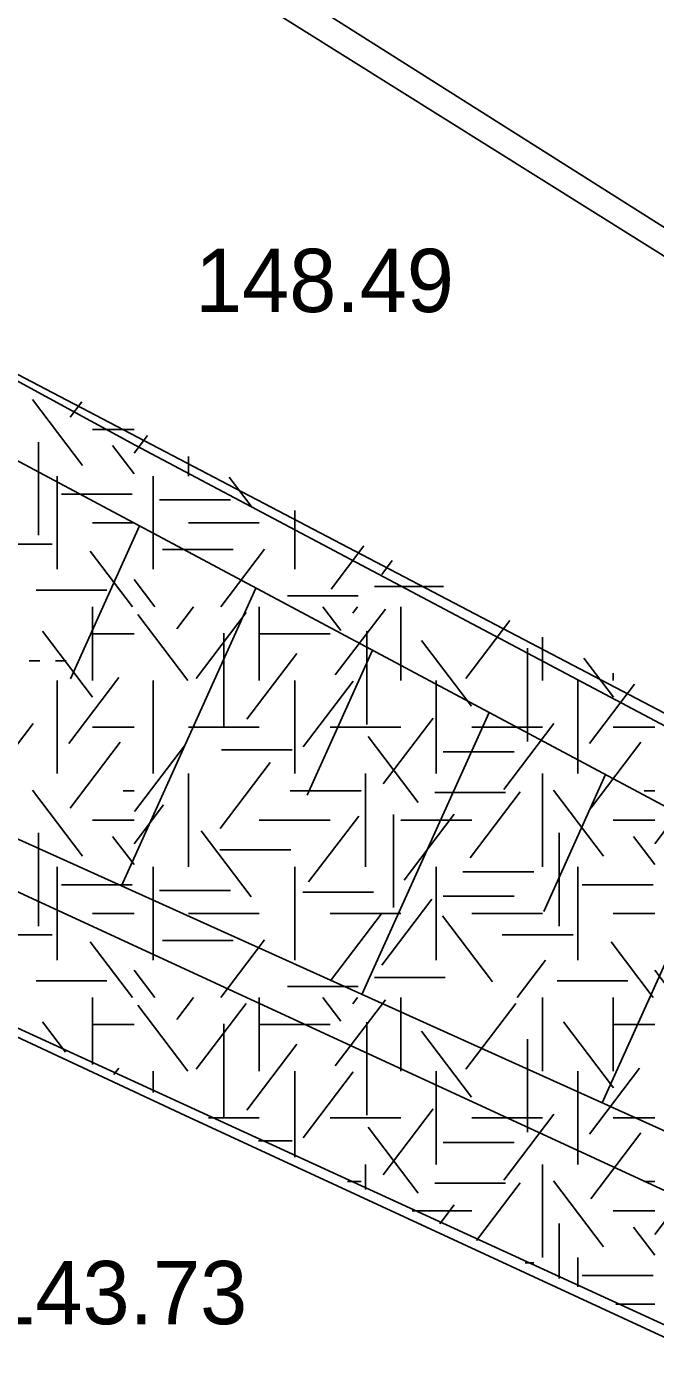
# Model space of a CAD drawing. Extents: x 419677 to 421689, y 4450851 to 4452923.
# Drawn here: x 420344.82 to 420356.74, y 4451978.52 to 4452004.01 of the extents above; entities that cross this region are included whole.
import ezdxf

# ---------------------------------------------------------------- set-up
doc = ezdxf.new("R2010")
doc.units = 0
for name, color, linetype in [('AA_HH', 7, 'Continuous'), ('Level 41', 7, 'Continuous'), ('Level 62', 7, 'Continuous'), ('Level 9', 7, 'Continuous')]:
    doc.layers.add(name, color=color, linetype=linetype)

msp = doc.modelspace()

# ---------------------------------------------------------------- linework, layer by layer
at = {"layer": 'AA_HH'}
for p, q in [((420346.954, 4451994.546), (420345.646, 4451991.646)), ((420349.165, 4451993.367), (420346.616, 4451987.719)), ((420351.375, 4451992.188), (420350.135, 4451989.439)), ((420344.863, 4451991.987), (420345.063, 4451991.987)), ((420345.363, 4451991.987), (420345.563, 4451991.987)), ((420353.586, 4451991.009), (420351.173, 4451985.662)), ((420355.797, 4451989.83), (420354.625, 4451987.232)), ((420358.008, 4451988.651), (420355.731, 4451983.606))]:
    msp.add_line(p, q, dxfattribs=at)
for points in [[(420420.283, 4451972.04), (420421.029, 4451970.095), (420421.342, 4451968.715), (420420.96, 4451967.485), (420420.456, 4451967.019), (420419.682, 4451966.656), (420419.467, 4451966.604), (420419.102, 4451966.589), (420380.556, 4451986.723), (420357.561, 4451999.25), (420318.688, 4452023.585), (420304.823, 4452033.943), (420285.337, 4452050.002), (420272.264, 4452064.398), (420263.435, 4452076.857), (420254.665, 4452090.863), (420245.178, 4452107.602), (420239.444, 4452119.113), (420237.151, 4452126.743), (420229.958, 4452160.587), (420223.737, 4452191.2), (420219.459, 4452205.797)], [(420397.569, 4451969.565), (420368.162, 4451984.791), (420346.871, 4451996.077), (420325.677, 4452007.623), (420307.1, 4452017.8), (420297.551, 4452023.383), (420287.987, 4452030.11), (420276.408, 4452038.563), (420264.859, 4452049.332), (420260.081, 4452053.957), (420259.882, 4452054.112), (420260.728, 4452041.699), (420259.985, 4452032.196), (420258.843, 4452024.529), (420255.051, 4452011.924), (420250.679, 4452002.57), (420243.311, 4451990.758), (420238.509, 4451984.736), (420246.006, 4451983.783), (420257.774, 4451981.835), (420271.403, 4451978.695), (420279.405, 4451976.372)], [(420438.02, 4451947.439), (420433.413, 4451950.307), (420401.754, 4451966.128), (420364.854, 4451984.999), (420328.536, 4452004.369), (420296.842, 4452019.746), (420270.508, 4452033.174), (420265.237, 4452035.449), (420263.701, 4452035.377)], [(420262.475, 4452026.146), (420281.038, 4452017.637), (420307.521, 4452005.58), (420333.161, 4451993.79), (420361.041, 4451981.209), (420384.615, 4451970.223), (420409.297, 4451959.288), (420435.147, 4451947.432), (420438.02, 4451947.439)], [(420497.355, 4451918.073), (420480.964, 4451925.058), (420460.145, 4451935.145), (420426.277, 4451950.923), (420396.304, 4451964.212), (420364.7, 4451978.35), (420337.466, 4451990.917), (420308.204, 4452004.292), (420278.592, 4452017.702), (420262.185, 4452024.997)], [(420261.585, 4452022.627), (420280.922, 4452013.915), (420311.822, 4452000.182), (420347.823, 4451983.366), (420379.279, 4451968.819), (420400.872, 4451959.31), (420439.168, 4451941.96), (420472.621, 4451926.744), (420501.172, 4451913.665)]]:
    msp.add_lwpolyline(points, dxfattribs=at)
at = {"layer": 'Level 41'}
for p, q in [((420345.878, 4451995.693), (420344.929, 4451996.942)), ((420345.639, 4451996.605), (420345.86, 4451996.896)), ((420346.064, 4451996.373), (420346.852, 4451996.373)), ((420346.852, 4451995.927), (420347.105, 4451996.26)), ((420345.039, 4451996.135), (420345.039, 4451994.367)), ((420346.852, 4451995.533), (420346.446, 4451996.067)), ((420347.885, 4451995.862), (420347.885, 4451995.49)), ((420345.393, 4451993.722), (420345.393, 4451995.49)), ((420347.214, 4451993.722), (420347.214, 4451995.49)), ((420349.072, 4451994.922), (420348.657, 4451995.468)), ((420345.475, 4451995.147), (420346.818, 4451995.147)), ((420347.337, 4451995.041), (420348.68, 4451995.041)), ((420349.9, 4451993.722), (420349.9, 4451994.834)), ((420346.064, 4451994.606), (420346.852, 4451994.606)), ((420347.885, 4451994.606), (420349.228, 4451994.606)), ((420343.957, 4451994.199), (420345.3, 4451994.199)), ((420346.823, 4451993.013), (420346.021, 4451994.069)), ((420347.391, 4451994.095), (420348.733, 4451994.095)), ((420348.499, 4451993.013), (420349.328, 4451994.104)), ((420350.59, 4451993.346), (420351.212, 4451994.165)), ((420351.55, 4451993.625), (420351.751, 4451993.89)), ((420347.246, 4451993.013), (420346.852, 4451993.531)), ((420344.996, 4451993.325), (420346.339, 4451993.325)), ((420349.761, 4451993.219), (420351.104, 4451993.219)), ((420351.413, 4451993.394), (420352.723, 4451993.394)), ((420346.064, 4451993.013), (420346.064, 4451991.615)), ((420346.064, 4451993.013), (420346.064, 4451991.615)), ((420347.662, 4451992.596), (420347.979, 4451993.013)), ((420349.228, 4451993.013), (420349.228, 4451991.615)), ((420350.777, 4451992.561), (420350.433, 4451993.013)), ((420350.67, 4451991.719), (420351.62, 4451992.969)), ((420351.003, 4451992.893), (420351.094, 4451993.013)), ((420351.914, 4451993.013), (420351.914, 4451991.615)), ((420347.873, 4451991.615), (420346.924, 4451992.865)), ((420348.033, 4451991.65), (420348.982, 4451992.9)), ((420353.147, 4451991.65), (420353.983, 4451992.751)), ((420346.065, 4451991.299), (420345.116, 4451992.548)), ((420346.064, 4451992.499), (420346.852, 4451992.499)), ((420348.553, 4451992.511), (420348.553, 4451990.744)), ((420349.228, 4451992.499), (420350.571, 4451992.499)), ((420351.27, 4451992.546), (420351.27, 4451990.779)), ((420354.6, 4451992.436), (420354.6, 4451991.615)), ((420353.254, 4451991.124), (420352.305, 4451992.373)), ((420354.318, 4451992.225), (420354.318, 4451990.458)), ((420348.993, 4451990.878), (420349.942, 4451992.128)), ((420355.944, 4451991.299), (420355.384, 4451992.036)), ((420345.613, 4451990.422), (420346.562, 4451991.672)), ((420355.943, 4451991.751), (420355.943, 4451991.615)), ((420355.943, 4451991.751), (420355.943, 4451991.615)), ((420345.393, 4451991.615), (420345.393, 4451989.848)), ((420345.393, 4451991.615), (420345.393, 4451989.848)), ((420347.214, 4451989.848), (420347.214, 4451991.615)), ((420349.9, 4451991.615), (420349.9, 4451989.848)), ((420350.059, 4451990.353), (420351.008, 4451991.603)), ((420352.586, 4451991.615), (420352.586, 4451989.848)), ((420355.272, 4451991.615), (420355.272, 4451989.848)), ((420355.272, 4451991.615), (420355.272, 4451989.848)), ((420355.492, 4451990.422), (420356.345, 4451991.546)), ((420351.576, 4451989.652), (420352.527, 4451990.901)), ((420343.988, 4451989.547), (420344.937, 4451990.797)), ((420346.064, 4451990.731), (420346.852, 4451990.731)), ((420347.885, 4451990.731), (420349.228, 4451990.731)), ((420350.571, 4451990.731), (420351.914, 4451990.731)), ((420353.257, 4451990.731), (420354.6, 4451990.731)), ((420353.867, 4451989.547), (420354.816, 4451990.797)), ((420355.943, 4451990.731), (420356.731, 4451990.731)), ((420345.639, 4451989.196), (420346.589, 4451990.445)), ((420352.242, 4451989.302), (420351.292, 4451990.551)), ((420355.518, 4451989.196), (420356.468, 4451990.445)), ((420346.862, 4451989.127), (420347.811, 4451990.376)), ((420348.509, 4451990.297), (420349.852, 4451990.297)), ((420352.717, 4451990.261), (420354.06, 4451990.261)), ((420348.487, 4451988.81), (420349.436, 4451990.06)), ((420347.885, 4451989.848), (420347.885, 4451988.081)), ((420351.243, 4451989.848), (420351.243, 4451988.081)), ((420354.6, 4451989.848), (420354.6, 4451988.081)), ((420345.878, 4451988.284), (420344.929, 4451989.533)), ((420346.648, 4451989.524), (420346.852, 4451989.524)), ((420349.815, 4451989.524), (420351.158, 4451989.524)), ((420352.557, 4451989.491), (420353.9, 4451989.491)), ((420353.227, 4451988.25), (420354.177, 4451989.5)), ((420355.757, 4451988.284), (420354.808, 4451989.533)), ((420356.527, 4451989.524), (420356.731, 4451989.524)), ((420346.852, 4451988.518), (420347.411, 4451989.254)), ((420356.731, 4451988.518), (420357.29, 4451989.254)), ((420346.064, 4451988.964), (420346.852, 4451988.964)), ((420349.228, 4451988.964), (420350.571, 4451988.964)), ((420350.164, 4451987.794), (420351.114, 4451989.044)), ((420351.775, 4451989.076), (420351.775, 4451987.308)), ((420351.914, 4451988.964), (420353.257, 4451988.964)), ((420351.975, 4451987.83), (420352.924, 4451989.079)), ((420355.943, 4451988.964), (420356.731, 4451988.964)), ((420345.039, 4451988.726), (420345.039, 4451986.958)), ((420346.852, 4451988.124), (420346.446, 4451988.658)), ((420349.072, 4451987.513), (420348.123, 4451988.763)), ((420354.918, 4451988.726), (420354.918, 4451986.958)), ((420356.731, 4451988.124), (420356.325, 4451988.658)), ((420348.482, 4451988.404), (420349.825, 4451988.404)), ((420345.393, 4451986.313), (420345.393, 4451988.081)), ((420347.214, 4451986.313), (420347.214, 4451988.081)), ((420349.9, 4451986.313), (420349.9, 4451988.081)), ((420352.586, 4451986.313), (420352.586, 4451988.081)), ((420353.091, 4451987.983), (420354.434, 4451987.983)), ((420355.272, 4451986.313), (420355.272, 4451988.081)), ((420345.475, 4451987.738), (420346.818, 4451987.738)), ((420347.337, 4451987.632), (420348.68, 4451987.632)), ((420350.054, 4451987.598), (420351.397, 4451987.598)), ((420355.354, 4451987.738), (420356.697, 4451987.738)), ((420351.55, 4451986.216), (420352.499, 4451987.466)), ((420352.717, 4451987.527), (420354.06, 4451987.527)), ((420346.064, 4451987.197), (420346.852, 4451987.197)), ((420347.885, 4451987.197), (420349.228, 4451987.197)), ((420350.571, 4451987.197), (420351.914, 4451987.197)), ((420350.59, 4451985.937), (420351.539, 4451987.186)), ((420353.653, 4451985.902), (420352.703, 4451987.151)), ((420353.257, 4451987.197), (420354.6, 4451987.197)), ((420355.943, 4451987.197), (420356.731, 4451987.197)), ((420343.957, 4451986.79), (420345.3, 4451986.79)), ((420346.823, 4451985.604), (420346.021, 4451986.66)), ((420347.391, 4451986.686), (420348.733, 4451986.686)), ((420348.499, 4451985.604), (420349.328, 4451986.695)), ((420353.836, 4451986.79), (420355.179, 4451986.79)), ((420356.702, 4451985.604), (420355.9, 4451986.66)), ((420354.119, 4451985.604), (420354.656, 4451986.31)), ((420347.246, 4451985.604), (420346.852, 4451986.122)), ((420357.125, 4451985.604), (420356.731, 4451986.122)), ((420344.996, 4451985.916), (420346.339, 4451985.916)), ((420349.761, 4451985.81), (420351.104, 4451985.81)), ((420351.413, 4451985.985), (420352.756, 4451985.985)), ((420354.875, 4451985.916), (420356.218, 4451985.916)), ((420346.064, 4451985.604), (420346.064, 4451984.33)), ((420346.064, 4451985.604), (420346.064, 4451984.33)), ((420347.662, 4451985.187), (420347.979, 4451985.604)), ((420349.228, 4451985.604), (420349.228, 4451984.206)), ((420350.777, 4451985.152), (420350.433, 4451985.604)), ((420350.67, 4451984.31), (420351.62, 4451985.56)), ((420351.003, 4451985.484), (420351.094, 4451985.604)), ((420351.914, 4451985.604), (420351.914, 4451984.206)), ((420354.6, 4451985.604), (420354.6, 4451984.206)), ((420355.943, 4451985.604), (420355.943, 4451984.206)), ((420355.943, 4451985.604), (420355.943, 4451984.206)), ((420347.873, 4451984.206), (420346.924, 4451985.456)), ((420348.033, 4451984.241), (420348.982, 4451985.491)), ((420353.147, 4451984.241), (420354.096, 4451985.491)), ((420345.553, 4451984.564), (420345.116, 4451985.139)), ((420346.064, 4451985.09), (420346.852, 4451985.09)), ((420348.553, 4451985.102), (420348.553, 4451983.335)), ((420349.228, 4451985.09), (420350.571, 4451985.09)), ((420351.27, 4451985.137), (420351.27, 4451983.37)), ((420355.944, 4451983.89), (420354.995, 4451985.139)), ((420355.943, 4451985.09), (420356.731, 4451985.09)), ((420353.254, 4451983.715), (420352.305, 4451984.964)), ((420354.318, 4451984.816), (420354.318, 4451983.049)), ((420348.993, 4451983.469), (420349.942, 4451984.719)), ((420346.471, 4451984.144), (420346.562, 4451984.263)), ((420355.492, 4451983.013), (420356.441, 4451984.263)), ((420347.214, 4451983.804), (420347.214, 4451984.206)), ((420349.9, 4451984.206), (420349.9, 4451982.574)), ((420350.059, 4451982.944), (420351.008, 4451984.194)), ((420352.586, 4451984.206), (420352.586, 4451982.439)), ((420355.272, 4451984.206), (420355.272, 4451982.439)), ((420355.272, 4451984.206), (420355.272, 4451982.439)), ((420348.267, 4451983.322), (420349.228, 4451983.322)), ((420350.571, 4451983.322), (420351.914, 4451983.322)), ((420351.576, 4451982.243), (420352.527, 4451983.492)), ((420353.257, 4451983.322), (420354.6, 4451983.322)), ((420353.867, 4451982.138), (420354.816, 4451983.388)), ((420355.943, 4451983.322), (420356.731, 4451983.322)), ((420352.242, 4451981.893), (420351.292, 4451983.142)), ((420355.518, 4451981.787), (420356.468, 4451983.036)), ((420349.215, 4451982.888), (420349.852, 4451982.888)), ((420352.717, 4451982.852), (420354.06, 4451982.852)), ((420351.243, 4451982.439), (420351.243, 4451981.96)), ((420354.6, 4451982.439), (420354.6, 4451980.672)), ((420350.904, 4451982.115), (420351.158, 4451982.115)), ((420352.557, 4451982.082), (420353.9, 4451982.082)), ((420353.346, 4451980.997), (420354.177, 4451982.091)), ((420355.757, 4451980.875), (420354.808, 4451982.124)), ((420356.527, 4451982.115), (420356.731, 4451982.115)), ((420356.731, 4451981.109), (420357.29, 4451981.845)), ((420352.127, 4451981.555), (420353.257, 4451981.555)), ((420352.654, 4451981.314), (420352.924, 4451981.67)), ((420355.943, 4451981.555), (420356.731, 4451981.555)), ((420354.918, 4451981.317), (420354.918, 4451980.278)), ((420356.731, 4451980.715), (420356.325, 4451981.249)), ((420354.27, 4451980.574), (420354.434, 4451980.574)), ((420355.272, 4451980.116), (420355.272, 4451980.672)), ((420355.354, 4451980.329), (420356.697, 4451980.329)), ((420355.988, 4451979.788), (420356.731, 4451979.788))]:
    msp.add_line(p, q, dxfattribs=at)
at = {"layer": 'Level 62'}
for p, q in [((420312.087, 4452014.455), (420412.275, 4451962.014)), ((420367.332, 4451974.612), (420327.12, 4451993.061))]:
    msp.add_line(p, q, dxfattribs=at)
at = {"layer": 'Level 9'}
for q in [(420295.814, 4452038.838), (420298.525, 4452037.123), (420298.525, 4452037.123)]:
    msp.add_line((420374.111, 4451989.328), q, dxfattribs=at)

# ---------------------------------------------------------------- texts
at = {"layer": 'AA_HH'}
msp.add_text('148.49 ', height=1.2, rotation=0.0026, dxfattribs=at).set_placement((420348.011, 4451998.599))
msp.add_text('143.73 ', height=1.2, dxfattribs=at).set_placement((420344.091, 4451979.408))

doc.saveas('drawing.dxf')
